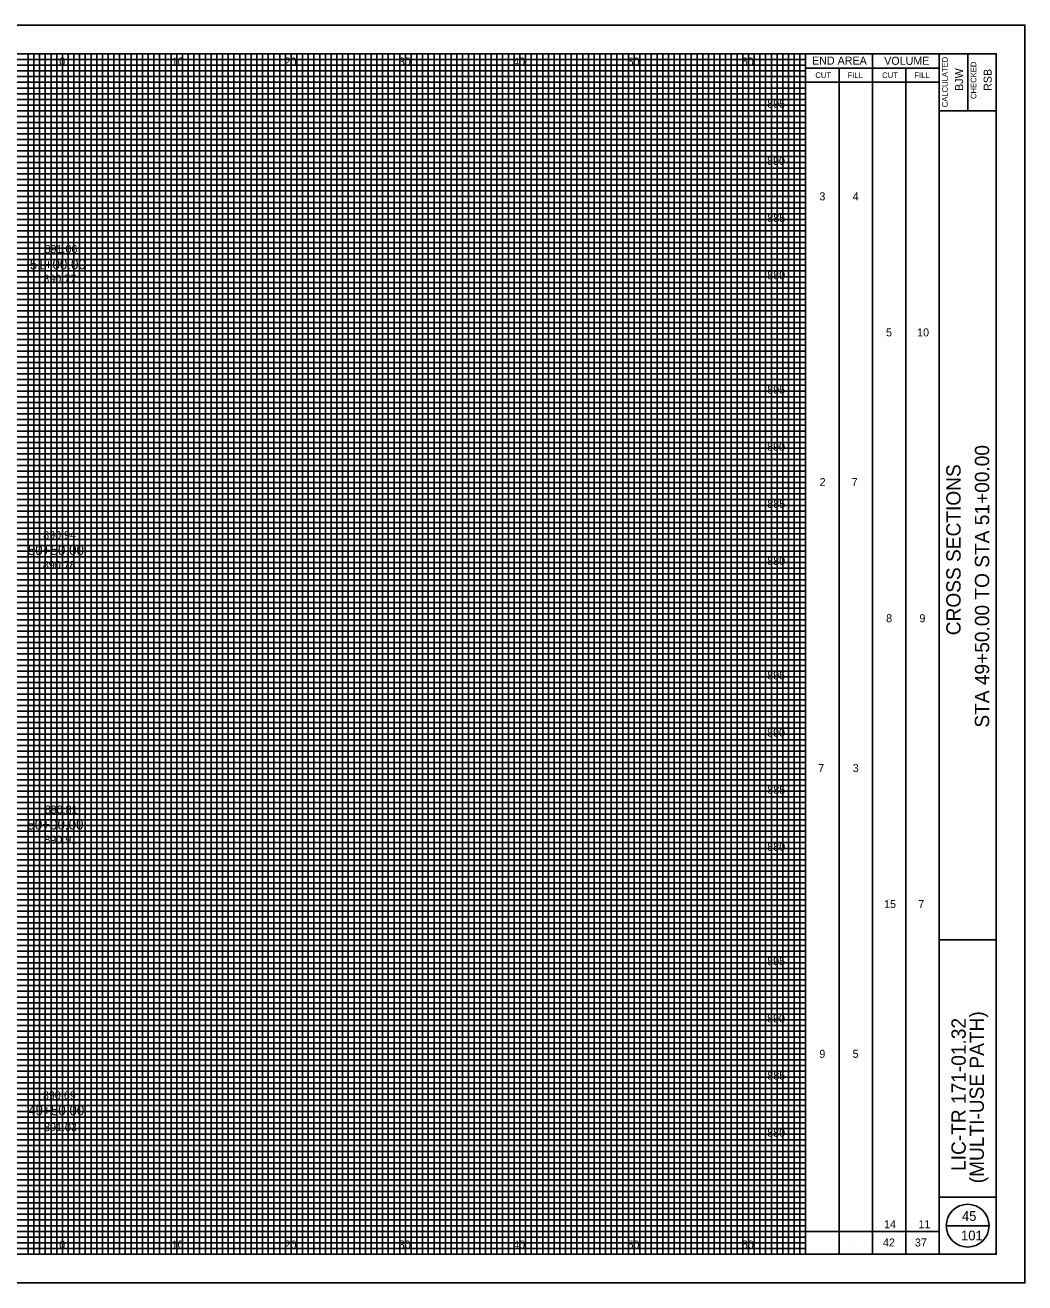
# Model space of a CAD drawing. Extents: x -10 to 160, y -2 to 2522.
# Drawn here: x 72.6 to 160, y 1952.5 to 2062.5 of the extents above; entities that cross this region are included whole.
import ezdxf

# ---------------------------------------------------------------- set-up
doc = ezdxf.new("R2010")
doc.units = 0
for name, color, linetype in [('GK_Cells', 7, 'Continuous'), ('GK_Patterns', 7, 'Continuous'), ('TX_P_10', 7, 'Continuous'), ('TX_X_10', 7, 'Continuous'), ('XS_P_Finished_Grade_Seeded', 7, 'Continuous'), ('XS_P_Pavt_Surface', 7, 'Continuous'), ('XS_P_Subgrade', 7, 'Continuous'), ('XS_X_Ground_Line', 7, 'Continuous')]:
    doc.layers.add(name, color=color, linetype=linetype)

msp = doc.modelspace()

# ---------------------------------------------------------------- linework, layer by layer
at = {"layer": 'GK_Cells'}
msp.add_lwpolyline([(-10, 1952.5), (160, 1952.5), (160, 2062.5), (-10, 2062.5)], close=True, dxfattribs=at)
at = {"layer": 'TX_P_10'}
for p, q in [((140.83, 1955), (140.83, 2060)), ((146.67, 1955), (146.67, 2060)), ((140.83, 2058.75), (152.5, 2058.75)), ((143.75, 1955), (143.75, 2058.75)), ((149.58, 1955), (149.58, 2058.75)), ((140.83, 2057.5), (152.5, 2057.5)), ((140.83, 1957), (152.5, 1957)), ((153.12, 1957.5), (156.88, 1957.5)), ((142.29, 1956), (142.29, 1956)), ((145.21, 1956), (145.21, 1956)), ((148.12, 1956), (148.12, 1956)), ((151.04, 1956), (151.04, 1956))]:
    msp.add_line(p, q, dxfattribs=at)
msp.add_circle((155, 1957.5), 1.87, dxfattribs=at)
at = {"layer": 'TX_X_10'}
for p, q in [((75.83, 1955), (75.83, 2060)), ((80.83, 1955), (80.83, 2060)), ((85.83, 1955), (85.83, 2060)), ((90.83, 1955), (90.83, 2060)), ((95.83, 1955), (95.83, 2060)), ((100.83, 1955), (100.83, 2060)), ((105.83, 1955), (105.83, 2060)), ((110.83, 1955), (110.83, 2060)), ((115.83, 1955), (115.83, 2060)), ((120.83, 1955), (120.83, 2060)), ((125.83, 1955), (125.83, 2060)), ((130.83, 1955), (130.83, 2060)), ((135.83, 1955), (135.83, 2060)), ((5.83, 2055), (140.83, 2055)), ((5.83, 2050), (140.83, 2050)), ((5.83, 2045), (140.83, 2045)), ((5.83, 2040), (140.83, 2040)), ((5.83, 2035), (140.83, 2035)), ((5.83, 2030), (140.83, 2030)), ((5.83, 2025), (140.83, 2025)), ((5.83, 2020), (140.83, 2020)), ((5.83, 2015), (140.83, 2015)), ((5.83, 2010), (140.83, 2010)), ((5.83, 2005), (140.83, 2005)), ((5.83, 2000), (140.83, 2000)), ((5.83, 1995), (140.83, 1995)), ((5.83, 1990), (140.83, 1990)), ((5.83, 1985), (140.83, 1985)), ((5.83, 1980), (140.83, 1980)), ((5.83, 1975), (140.83, 1975)), ((5.83, 1970), (140.83, 1970)), ((5.83, 1965), (140.83, 1965)), ((5.83, 1960), (140.83, 1960))]:
    msp.add_line(p, q, dxfattribs=at)
at = {"layer": 'XS_P_Pavt_Surface'}
for p, q in [((152.5, 1955), (152.5, 2060)), ((155, 2060), (155, 2055)), ((152.5, 2055), (157.5, 2055)), ((152.5, 1982.5), (157.5, 1982.5)), ((152.5, 1960), (157.5, 1960))]:
    msp.add_line(p, q, dxfattribs=at)
msp.add_lwpolyline([(0, 2060), (157.5, 2060), (157.5, 1955), (0, 1955)], close=True, dxfattribs=at)
at = {"layer": 'XS_X_Ground_Line'}
for p, q in [((5.83, 2059.5), (140.83, 2059.5)), ((72.83, 1955), (72.83, 2060)), ((73.33, 1955), (73.33, 2060)), ((73.83, 1955), (73.83, 2060)), ((74.33, 1955), (74.33, 2060)), ((74.83, 1955), (74.83, 2060)), ((75.33, 1955), (75.33, 2060)), ((76.33, 1955), (76.33, 2060)), ((76.83, 1955), (76.83, 2060)), ((77.33, 1955), (77.33, 2060)), ((77.83, 1955), (77.83, 2060)), ((78.33, 1955), (78.33, 2060)), ((78.83, 1955), (78.83, 2060)), ((79.33, 1955), (79.33, 2060)), ((79.83, 1955), (79.83, 2060)), ((80.33, 1955), (80.33, 2060)), ((81.33, 1955), (81.33, 2060)), ((81.83, 1955), (81.83, 2060)), ((82.33, 1955), (82.33, 2060)), ((82.83, 1955), (82.83, 2060)), ((83.33, 1955), (83.33, 2060)), ((83.83, 1955), (83.83, 2060)), ((84.33, 1955), (84.33, 2060)), ((84.83, 1955), (84.83, 2060)), ((85.33, 1955), (85.33, 2060)), ((86.33, 1955), (86.33, 2060)), ((86.83, 1955), (86.83, 2060)), ((87.33, 1955), (87.33, 2060)), ((87.83, 1955), (87.83, 2060)), ((88.33, 1955), (88.33, 2060)), ((88.83, 1955), (88.83, 2060)), ((89.33, 1955), (89.33, 2060)), ((89.83, 1955), (89.83, 2060)), ((90.33, 1955), (90.33, 2060)), ((91.33, 1955), (91.33, 2060)), ((91.83, 1955), (91.83, 2060)), ((92.33, 1955), (92.33, 2060)), ((92.83, 1955), (92.83, 2060)), ((93.33, 1955), (93.33, 2060)), ((93.83, 1955), (93.83, 2060)), ((94.33, 1955), (94.33, 2060)), ((94.83, 1955), (94.83, 2060)), ((95.33, 1955), (95.33, 2060)), ((96.33, 1955), (96.33, 2060)), ((96.83, 1955), (96.83, 2060)), ((97.33, 1955), (97.33, 2060)), ((97.83, 1955), (97.83, 2060)), ((98.33, 1955), (98.33, 2060)), ((98.83, 1955), (98.83, 2060)), ((99.33, 1955), (99.33, 2060)), ((99.83, 1955), (99.83, 2060)), ((100.33, 1955), (100.33, 2060)), ((101.33, 1955), (101.33, 2060)), ((101.83, 1955), (101.83, 2060)), ((102.33, 1955), (102.33, 2060)), ((102.83, 1955), (102.83, 2060)), ((103.33, 1955), (103.33, 2060)), ((103.83, 1955), (103.83, 2060)), ((104.33, 1955), (104.33, 2060)), ((104.83, 1955), (104.83, 2060)), ((105.33, 1955), (105.33, 2060)), ((106.33, 1955), (106.33, 2060)), ((106.83, 1955), (106.83, 2060)), ((107.33, 1955), (107.33, 2060)), ((107.83, 1955), (107.83, 2060)), ((108.33, 1955), (108.33, 2060)), ((108.83, 1955), (108.83, 2060)), ((109.33, 1955), (109.33, 2060)), ((109.83, 1955), (109.83, 2060)), ((110.33, 1955), (110.33, 2060)), ((111.33, 1955), (111.33, 2060)), ((111.83, 1955), (111.83, 2060)), ((112.33, 1955), (112.33, 2060)), ((112.83, 1955), (112.83, 2060)), ((113.33, 1955), (113.33, 2060)), ((113.83, 1955), (113.83, 2060)), ((114.33, 1955), (114.33, 2060)), ((114.83, 1955), (114.83, 2060)), ((115.33, 1955), (115.33, 2060)), ((116.33, 1955), (116.33, 2060)), ((116.83, 1955), (116.83, 2060)), ((117.33, 1955), (117.33, 2060)), ((117.83, 1955), (117.83, 2060)), ((118.33, 1955), (118.33, 2060)), ((118.83, 1955), (118.83, 2060)), ((119.33, 1955), (119.33, 2060)), ((119.83, 1955), (119.83, 2060)), ((120.33, 1955), (120.33, 2060)), ((121.33, 1955), (121.33, 2060)), ((121.83, 1955), (121.83, 2060)), ((122.33, 1955), (122.33, 2060)), ((122.83, 1955), (122.83, 2060)), ((123.33, 1955), (123.33, 2060)), ((123.83, 1955), (123.83, 2060)), ((124.33, 1955), (124.33, 2060)), ((124.83, 1955), (124.83, 2060)), ((125.33, 1955), (125.33, 2060)), ((126.33, 1955), (126.33, 2060)), ((126.83, 1955), (126.83, 2060)), ((127.33, 1955), (127.33, 2060)), ((127.83, 1955), (127.83, 2060)), ((128.33, 1955), (128.33, 2060)), ((128.83, 1955), (128.83, 2060)), ((129.33, 1955), (129.33, 2060)), ((129.83, 1955), (129.83, 2060)), ((130.33, 1955), (130.33, 2060)), ((131.33, 1955), (131.33, 2060)), ((131.83, 1955), (131.83, 2060)), ((132.33, 1955), (132.33, 2060)), ((132.83, 1955), (132.83, 2060)), ((133.33, 1955), (133.33, 2060)), ((133.83, 1955), (133.83, 2060)), ((134.33, 1955), (134.33, 2060)), ((134.83, 1955), (134.83, 2060)), ((135.33, 1955), (135.33, 2060)), ((136.33, 1955), (136.33, 2060)), ((136.83, 1955), (136.83, 2060)), ((137.33, 1955), (137.33, 2060)), ((137.83, 1955), (137.83, 2060)), ((138.33, 1955), (138.33, 2060)), ((138.83, 1955), (138.83, 2060)), ((139.33, 1955), (139.33, 2060)), ((139.83, 1955), (139.83, 2060)), ((140.33, 1955), (140.33, 2060)), ((5.83, 2059), (140.83, 2059)), ((5.83, 2058.5), (140.83, 2058.5)), ((5.83, 2058), (140.83, 2058)), ((5.83, 2057.5), (140.83, 2057.5)), ((5.83, 2057), (140.83, 2057)), ((5.83, 2056.5), (140.83, 2056.5)), ((5.83, 2056), (140.83, 2056)), ((5.83, 2055.5), (140.83, 2055.5)), ((5.83, 2054.5), (140.83, 2054.5)), ((5.83, 2054), (140.83, 2054)), ((5.83, 2053.5), (140.83, 2053.5)), ((5.83, 2053), (140.83, 2053)), ((5.83, 2052.5), (140.83, 2052.5)), ((5.83, 2052), (140.83, 2052)), ((5.83, 2051.5), (140.83, 2051.5)), ((5.83, 2051), (140.83, 2051)), ((5.83, 2050.5), (140.83, 2050.5)), ((5.83, 2049.5), (140.83, 2049.5)), ((5.83, 2049), (140.83, 2049)), ((5.83, 2048.5), (140.83, 2048.5)), ((5.83, 2048), (140.83, 2048)), ((5.83, 2047.5), (140.83, 2047.5)), ((5.83, 2047), (140.83, 2047)), ((5.83, 2046.5), (140.83, 2046.5)), ((5.83, 2046), (140.83, 2046)), ((5.83, 2045.5), (140.83, 2045.5)), ((5.83, 2044.5), (140.83, 2044.5)), ((5.83, 2044), (140.83, 2044)), ((5.83, 2043.5), (140.83, 2043.5)), ((5.83, 2043), (140.83, 2043)), ((5.83, 2042.5), (140.83, 2042.5)), ((5.83, 2042), (140.83, 2042)), ((5.83, 2041.5), (140.83, 2041.5)), ((5.83, 2041), (140.83, 2041)), ((5.83, 2040.5), (140.83, 2040.5)), ((5.83, 2039.5), (140.83, 2039.5)), ((5.83, 2039), (140.83, 2039)), ((5.83, 2038.5), (140.83, 2038.5)), ((5.83, 2038), (140.83, 2038)), ((5.83, 2037.5), (140.83, 2037.5)), ((5.83, 2037), (140.83, 2037)), ((5.83, 2036.5), (140.83, 2036.5)), ((5.83, 2036), (140.83, 2036)), ((5.83, 2035.5), (140.83, 2035.5)), ((5.83, 2034.5), (140.83, 2034.5)), ((5.83, 2034), (140.83, 2034)), ((5.83, 2033.5), (140.83, 2033.5)), ((5.83, 2033), (140.83, 2033)), ((5.83, 2032.5), (140.83, 2032.5)), ((5.83, 2032), (140.83, 2032)), ((5.83, 2031.5), (140.83, 2031.5)), ((5.83, 2031), (140.83, 2031)), ((5.83, 2030.5), (140.83, 2030.5)), ((5.83, 2029.5), (140.83, 2029.5)), ((5.83, 2029), (140.83, 2029)), ((5.83, 2028.5), (140.83, 2028.5)), ((5.83, 2028), (140.83, 2028)), ((5.83, 2027.5), (140.83, 2027.5)), ((5.83, 2027), (140.83, 2027)), ((5.83, 2026.5), (140.83, 2026.5)), ((5.83, 2026), (140.83, 2026)), ((5.83, 2025.5), (140.83, 2025.5)), ((5.83, 2024.5), (140.83, 2024.5)), ((5.83, 2024), (140.83, 2024)), ((5.83, 2023.5), (140.83, 2023.5)), ((5.83, 2023), (140.83, 2023)), ((5.83, 2022.5), (140.83, 2022.5)), ((5.83, 2022), (140.83, 2022)), ((5.83, 2021.5), (140.83, 2021.5)), ((5.83, 2021), (140.83, 2021)), ((5.83, 2020.5), (140.83, 2020.5)), ((5.83, 2019.5), (140.83, 2019.5)), ((5.83, 2019), (140.83, 2019)), ((5.83, 2018.5), (140.83, 2018.5)), ((5.83, 2018), (140.83, 2018)), ((5.83, 2017.5), (140.83, 2017.5)), ((5.83, 2017), (140.83, 2017)), ((5.83, 2016.5), (140.83, 2016.5)), ((5.83, 2016), (140.83, 2016)), ((5.83, 2015.5), (140.83, 2015.5)), ((5.83, 2014.5), (140.83, 2014.5)), ((5.83, 2014), (140.83, 2014)), ((5.83, 2013.5), (140.83, 2013.5)), ((5.83, 2013), (140.83, 2013)), ((5.83, 2012.5), (140.83, 2012.5)), ((5.83, 2012), (140.83, 2012)), ((5.83, 2011.5), (140.83, 2011.5)), ((5.83, 2011), (140.83, 2011)), ((5.83, 2010.5), (140.83, 2010.5)), ((5.83, 2009.5), (140.83, 2009.5)), ((5.83, 2009), (140.83, 2009)), ((5.83, 2008.5), (140.83, 2008.5)), ((5.83, 2008), (140.83, 2008)), ((5.83, 2007.5), (140.83, 2007.5)), ((5.83, 2007), (140.83, 2007)), ((5.83, 2006.5), (140.83, 2006.5)), ((5.83, 2006), (140.83, 2006)), ((5.83, 2005.5), (140.83, 2005.5)), ((5.83, 2004.5), (140.83, 2004.5)), ((5.83, 2004), (140.83, 2004)), ((5.83, 2003.5), (140.83, 2003.5)), ((5.83, 2003), (140.83, 2003)), ((5.83, 2002.5), (140.83, 2002.5)), ((5.83, 2002), (140.83, 2002)), ((5.83, 2001.5), (140.83, 2001.5)), ((5.83, 2001), (140.83, 2001)), ((5.83, 2000.5), (140.83, 2000.5)), ((5.83, 1999.5), (140.83, 1999.5)), ((5.83, 1999), (140.83, 1999)), ((5.83, 1998.5), (140.83, 1998.5)), ((5.83, 1998), (140.83, 1998)), ((5.83, 1997.5), (140.83, 1997.5)), ((5.83, 1997), (140.83, 1997)), ((5.83, 1996.5), (140.83, 1996.5)), ((5.83, 1996), (140.83, 1996)), ((5.83, 1995.5), (140.83, 1995.5)), ((5.83, 1994.5), (140.83, 1994.5)), ((5.83, 1994), (140.83, 1994)), ((5.83, 1993.5), (140.83, 1993.5)), ((5.83, 1993), (140.83, 1993)), ((5.83, 1992.5), (140.83, 1992.5)), ((5.83, 1992), (140.83, 1992)), ((5.83, 1991.5), (140.83, 1991.5)), ((5.83, 1991), (140.83, 1991)), ((5.83, 1990.5), (140.83, 1990.5)), ((5.83, 1989.5), (140.83, 1989.5)), ((5.83, 1989), (140.83, 1989)), ((5.83, 1988.5), (140.83, 1988.5)), ((5.83, 1988), (140.83, 1988)), ((5.83, 1987.5), (140.83, 1987.5)), ((5.83, 1987), (140.83, 1987)), ((5.83, 1986.5), (140.83, 1986.5)), ((5.83, 1986), (140.83, 1986)), ((5.83, 1985.5), (140.83, 1985.5)), ((5.83, 1984.5), (140.83, 1984.5)), ((5.83, 1984), (140.83, 1984)), ((5.83, 1983.5), (140.83, 1983.5)), ((5.83, 1983), (140.83, 1983)), ((5.83, 1982.5), (140.83, 1982.5)), ((5.83, 1982), (140.83, 1982)), ((5.83, 1981.5), (140.83, 1981.5)), ((5.83, 1981), (140.83, 1981)), ((5.83, 1980.5), (140.83, 1980.5)), ((5.83, 1979.5), (140.83, 1979.5)), ((5.83, 1979), (140.83, 1979)), ((5.83, 1978.5), (140.83, 1978.5)), ((5.83, 1978), (140.83, 1978)), ((5.83, 1977.5), (140.83, 1977.5)), ((5.83, 1977), (140.83, 1977)), ((5.83, 1976.5), (140.83, 1976.5)), ((5.83, 1976), (140.83, 1976)), ((5.83, 1975.5), (140.83, 1975.5)), ((5.83, 1974.5), (140.83, 1974.5)), ((5.83, 1974), (140.83, 1974)), ((5.83, 1973.5), (140.83, 1973.5)), ((5.83, 1973), (140.83, 1973)), ((5.83, 1972.5), (140.83, 1972.5)), ((5.83, 1972), (140.83, 1972)), ((5.83, 1971.5), (140.83, 1971.5)), ((5.83, 1971), (140.83, 1971)), ((5.83, 1970.5), (140.83, 1970.5)), ((5.83, 1969.5), (140.83, 1969.5)), ((5.83, 1969), (140.83, 1969)), ((5.83, 1968.5), (140.83, 1968.5)), ((5.83, 1968), (140.83, 1968)), ((5.83, 1967.5), (140.83, 1967.5)), ((5.83, 1967), (140.83, 1967)), ((5.83, 1966.5), (140.83, 1966.5)), ((5.83, 1966), (140.83, 1966)), ((5.83, 1965.5), (140.83, 1965.5)), ((5.83, 1964.5), (140.83, 1964.5)), ((5.83, 1964), (140.83, 1964)), ((5.83, 1963.5), (140.83, 1963.5)), ((5.83, 1963), (140.83, 1963)), ((5.83, 1962.5), (140.83, 1962.5)), ((5.83, 1962), (140.83, 1962)), ((5.83, 1961.5), (140.83, 1961.5)), ((5.83, 1961), (140.83, 1961)), ((5.83, 1960.5), (140.83, 1960.5)), ((5.83, 1959.5), (140.83, 1959.5)), ((5.83, 1959), (140.83, 1959)), ((5.83, 1958.5), (140.83, 1958.5)), ((5.83, 1958), (140.83, 1958)), ((5.83, 1957.5), (140.83, 1957.5)), ((5.83, 1957), (140.83, 1957)), ((5.83, 1956.5), (140.83, 1956.5)), ((5.83, 1956), (140.83, 1956)), ((5.83, 1955.5), (140.83, 1955.5))]:
    msp.add_line(p, q, dxfattribs=at)

# ---------------------------------------------------------------- texts
at = {"layer": 'GK_Patterns'}
for s, height, p in [('0', 0.7, (75.55, 2058.97)), ('0', 0.7, (75.55, 2058.97)), ('10', 0.7, (85.39, 2058.97)), ('20', 0.7, (95.26, 2058.97)), ('30', 0.7, (105.25, 2058.97)), ('40', 0.7, (115.25, 2058.97)), ('50', 0.7, (125.25, 2058.97)), ('60', 0.7, (135.25, 2058.97)), ('895', 0.7, (137.47, 2055.28)), ('890', 0.7, (137.46, 2050.28)), ('3', 0.7, (142.03, 2047.18)), ('4', 0.7, (144.94, 2047.18)), ('885', 0.7, (137.48, 2045.28)), ('51+00.00', 0.875, (72.97, 2041.15)), ('880', 0.7, (137.47, 2040.28)), ('5', 0.7, (147.86, 2035.28)), ('10', 0.7, (150.58, 2035.28)), ('895', 0.7, (137.47, 2030.28)), ('890', 0.7, (137.46, 2025.28)), ('2', 0.7, (142.05, 2022.18)), ('7', 0.7, (144.85, 2022.18)), ('885', 0.7, (137.48, 2020.28)), ('50+50.00', 0.875, (72.8, 2016.15)), ('880', 0.7, (137.47, 2015.28)), ('8', 0.7, (147.87, 2010.28)), ('9', 0.7, (150.78, 2010.28)), ('895', 0.7, (137.47, 2005.28)), ('890', 0.7, (137.46, 2000.28)), ('7', 0.7, (141.93, 1997.18)), ('3', 0.7, (144.95, 1997.18)), ('885', 0.7, (137.48, 1995.28)), ('50+00.00', 0.875, (72.76, 1992.15)), ('880', 0.7, (137.47, 1990.28)), ('15', 0.7, (147.69, 1985.28)), ('7', 0.7, (150.68, 1985.28)), ('895', 0.7, (137.47, 1980.28)), ('890', 0.7, (137.46, 1975.28)), ('9', 0.7, (142.03, 1972.18)), ('5', 0.7, (144.94, 1972.18)), ('885', 0.7, (137.48, 1970.28)), ('49+50.00', 0.875, (72.83, 1967.15)), ('880', 0.7, (137.47, 1965.28)), ('14', 0.7, (147.69, 1957.28)), ('11', 0.7, (150.7, 1957.28)), ('0', 0.7, (75.55, 1955.5)), ('0', 0.7, (75.55, 1955.5)), ('10', 0.7, (85.39, 1955.5)), ('20', 0.7, (95.26, 1955.5)), ('30', 0.7, (105.25, 1955.5)), ('40', 0.7, (115.25, 1955.5)), ('50', 0.7, (125.25, 1955.5)), ('60', 0.7, (135.25, 1955.5)), ('42', 0.7, (147.59, 1955.68)), ('37', 0.7, (150.39, 1955.68))]:
    msp.add_text(s, height=height, dxfattribs=at).set_placement(p)
at = {"layer": 'TX_P_10'}
for s, height, p in [('END AREA', 0.7, (141.39, 2059.05)), ('VOLUME', 0.7, (147.7, 2059.03)), ('CUT', 0.5, (141.68, 2057.87)), ('FILL', 0.5, (144.5, 2057.87)), ('CUT', 0.5, (147.52, 2057.87)), ('FILL', 0.5, (150.34, 2057.87)), ('45', 0.85, (154.5, 1957.92)), ('101', 0.85, (154.42, 1956.22))]:
    msp.add_text(s, height=height, dxfattribs=at).set_placement(p)
for s, height, p in [('CALCULATED', 0.5, (153.26, 2055.32)), ('CHECKED', 0.5, (155.76, 2056.04)), ('BJW', 0.7, (154.6, 2056.75)), ('RSB', 0.7, (157.1, 2056.75)), ('STA 49+50.00 TO STA 51+00.00', 1.25, (156.88, 2001.06)), ('CROSS SECTIONS', 1.25, (154.38, 2009.14)), ('(MULTI-USE PATH)', 1.25, (156.42, 1961.21)), ('LIC-TR 171-01.32', 1.25, (154.83, 1962.29))]:
    msp.add_text(s, height=height, rotation=90, dxfattribs=at).set_placement(p)
at = {"layer": 'XS_P_Finished_Grade_Seeded'}
for s, p in [('890.77', (74.16, 2039.97)), ('890.78', (74.12, 2014.94)), ('890.91', (74.25, 1990.91)), ('891.03', (74.23, 1965.77))]:
    msp.add_text(s, height=0.7, dxfattribs=at).set_placement(p)
at = {"layer": 'XS_P_Subgrade'}
for s, p in [('891.06', (74.27, 2042.57)), ('890.94', (74.15, 2017.56)), ('890.81', (74.29, 1993.55)), ('890.69', (74.13, 1968.55))]:
    msp.add_text(s, height=0.7, dxfattribs=at).set_placement(p)

doc.saveas('drawing.dxf')
